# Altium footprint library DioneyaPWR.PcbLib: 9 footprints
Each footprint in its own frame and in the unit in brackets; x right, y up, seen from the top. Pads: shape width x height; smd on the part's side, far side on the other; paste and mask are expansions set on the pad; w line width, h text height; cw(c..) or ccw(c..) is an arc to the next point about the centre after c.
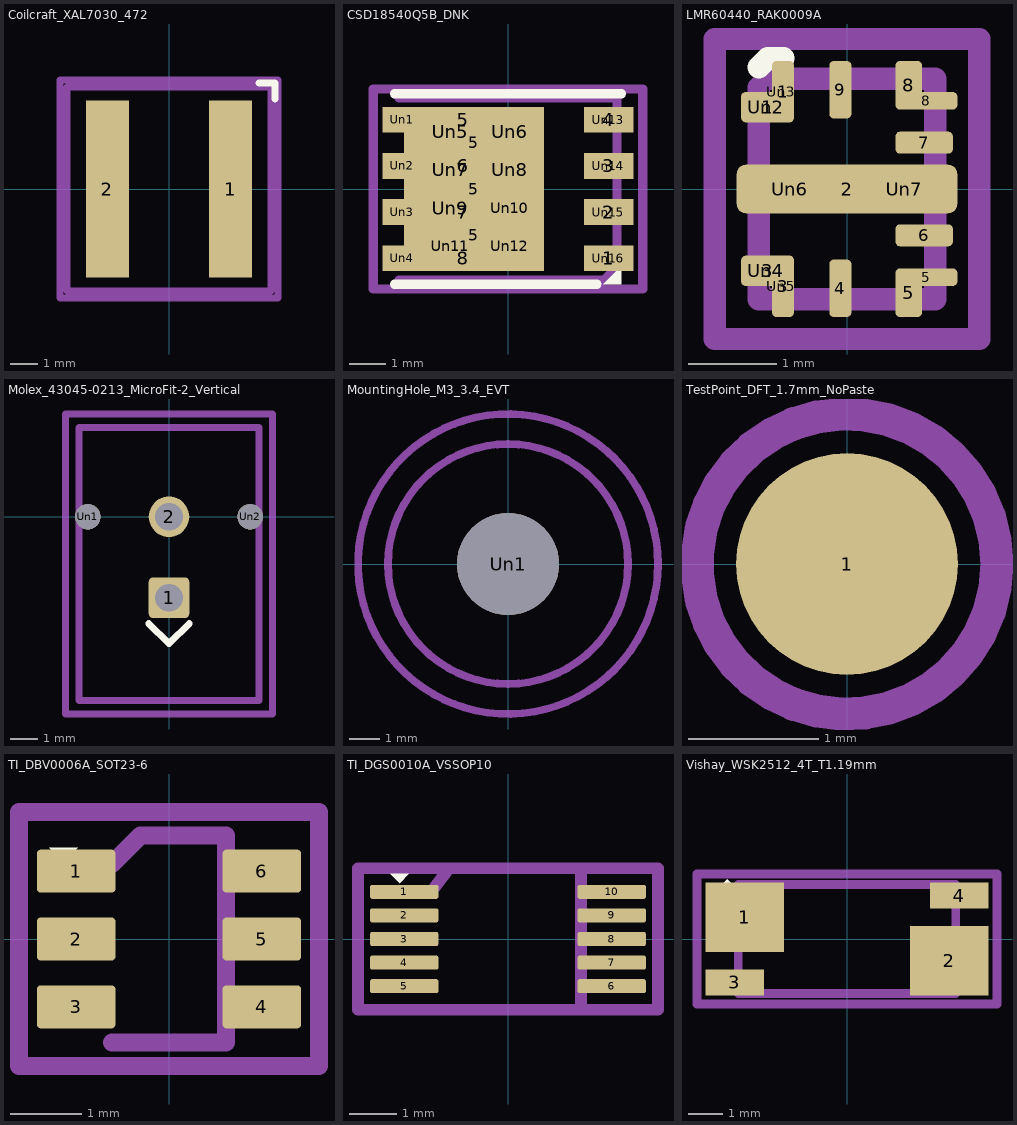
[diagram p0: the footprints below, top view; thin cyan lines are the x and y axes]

## Coilcraft_XAL7030_472 [mm]
pads (2):
  rect 1.58x6.5 smd: 1(2.26,0) 2(-2.26,0)
F.SilkS:
  lines w0.254: 3.3,3.9 3.9,3.9 3.9,3.3
F.Fab:
  lines w0.254: -3.75,-3.75 -3.75,3.75 3.75,3.75 3.75,-3.75 -3.75,-3.75
F.CrtYd:
  lines w0.254: -4,-4 -4,4 4,4 4,-4 -4,-4

## CSD18540Q5B_DNK [mm]
pads (27):
  rect 1.372x0.71 smd: 1(2.77,-1.905) 2(2.77,-0.635) 3(2.77,0.635) 4(2.77,1.905)
  rect 4.44x0.71 smd: 5(-1.236,1.905) 6(-1.236,0.635) 7(-1.236,-0.635) 8(-1.236,-1.905)
  rect 3.85x0.56 smd: 5(-0.941,-1.27) 5(-0.941,0) 5(-0.941,1.27)
  rect 0.766x0.508 on Top Paste: Un1(-2.91,1.905) Un2(-2.91,0.635) Un3(-2.91,-0.635) Un4(-2.91,-1.905)
  rect 1.294x0.746 on Top Paste: Un5(-1.594,1.569) Un6(0.05,1.569) Un7(-1.594,0.523) Un8(0.05,0.523) Un9(-1.594,-0.523) Un10(0.05,-0.523) Un11(-1.594,-1.569) Un12(0.05,-1.569)
  rect 1.072x0.562 on Top Paste: Un13(2.758,1.905) Un14(2.758,0.635) Un15(2.758,-0.635) Un16(2.758,-1.905)
F.SilkS:
  region: 3.12,-2.62 2.62,-2.62 3.12,-2.12
  lines w0.254: -3.12,-2.62 2.45,-2.62 ; -3.12,2.62 3.12,2.62
F.Fab:
  lines w0.254: -3,-2.5 2.65,-2.5 3,-2.15 3,2.5 -3,2.5
F.CrtYd:
  lines w0.254: -3.706,-2.75 -3.706,2.75 3.706,2.75 3.706,-2.75 -3.706,-2.75

## LMR60440_RAK0009A [mm]
pads (20):
  rrect29% 0.6x0.345 smd: 1(-0.9,0.927) 3(-0.9,-0.927)
  rrect40% 0.25x0.695 smd: 1(-0.725,1.102) 3(-0.725,-1.102)
  rrect36% 2.5x0.55 smd: 2(0,0)
  rrect40% 0.25x0.65 smd: 4(-0.075,-1.125) 9(-0.075,1.125)
  rrect33% 0.3x0.55 smd: 5(0.7,-1.175) 8(0.7,1.175)
  rrect50% 0.7x0.2 smd: 5(0.9,-1) 8(0.9,1)
  rrect40% 0.65x0.25 smd: 6(0.875,-0.525) 7(0.875,0.525)
  rect 0.01x0.01 on Top Solder: Un1(0,0)
  rrect29% 0.56x0.345 on Top Paste: Un2(-0.92,0.927) Un4(-0.92,-0.927)
  rrect48% 0.21x0.695 on Top Paste: Un3(-0.745,1.102) Un5(-0.745,-1.102)
  rrect24% 1.1x0.41 on Top Paste: Un6(-0.65,0)
  rrect33% 1.1x0.3 on Top Paste: Un7(0.65,0)
F.SilkS:
  lines w0.254: -1,1.38 -0.9,1.48 -0.72,1.48
F.Mask:
  region: -0.027,0.214 0.037,0.161 0.069,0.15 1.15,0.15 1.2,0.1 1.2,-0.1 1.15,-0.15 0.069,-0.15 0.037,-0.161 -0.027,-0.214 -0.059,-0.225 -1.15,-0.225 -1.2,-0.175 -1.2,0.175 -1.15,0.225 -0.059,0.225
F.Fab:
  lines w0.254: -1,1.15 -1,-1.25 1,-1.25 1,1.25 -0.9,1.25
F.CrtYd:
  lines w0.254: -1.5,-1.7 -1.5,1.7 1.5,1.7 1.5,-1.7 -1.5,-1.7

## Molex_43045-0213_MicroFit-2_Vertical [mm]
pads (4):
  rrect20% 1.5x1.5 hole 1.02: 1(0,-3)
  round 1.5 hole 1.02: 2(0,0)
  round 0.94 hole 0.94: Un1(-3,0) Un2(3,0)
F.SilkS:
  lines w0.254: -0.75,-3.95 0,-4.7 0.75,-3.95
F.Fab:
  lines w0.254: -3.325,-6.8 -3.325,3.3 3.325,3.3 3.325,-6.8 -3.325,-6.8
F.CrtYd:
  lines w0.254: -3.83,-7.3 -3.83,3.8 3.83,3.8 3.83,-7.3 -3.83,-7.3

## MountingHole_M3_3.4_EVT [mm]
pads (1):
  round 3.4 hole 3.4: Un1(0,0)
F.CrtYd:
  circle w0.254: c0,0 r5
Dwgs.User:
  circle w0.254: c0,0 r4

## TestPoint_DFT_1.7mm_NoPaste [mm]
pads (1):
  round 1.7 smd: 1(0,0)
F.CrtYd:
  circle w0.254: c0,0 r1.15

## TI_DBV0006A_SOT23-6 [mm]
pads (6):
  rrect17% 1.1x0.6 smd: 1(-1.3,0.95) 2(-1.3,0) 3(-1.3,-0.95) 4(1.3,-0.95) 5(1.3,0) 6(1.3,0.95)
F.SilkS:
  region: -1.48,1.08 -1.68,1.28 -1.28,1.28
F.Fab:
  lines w0.254: -0.8,-1.45 0.8,-1.45 0.8,1.45 -0.4,1.45 -0.8,1.05
F.CrtYd:
  lines w0.254: -2.1,-1.78 -2.1,1.78 2.1,1.78 2.1,-1.78 -2.1,-1.78

## TI_DGS0010A_VSSOP10 [mm]
pads (10):
  rrect33% 1.45x0.3 smd: 1(-2.2,1) 2(-2.2,0.5) 3(-2.2,0) 4(-2.2,-0.5) 5(-2.2,-1) 6(2.2,-1) 7(2.2,-0.5) 8(2.2,0) 9(2.2,0.5) 10(2.2,1)
F.SilkS:
  region: -2.3,1.18 -2.5,1.38 -2.1,1.38
F.Fab:
  lines w0.254: -1.55,-1.5 1.55,-1.5 1.55,1.5 -1.25,1.5 -1.55,1.1
F.CrtYd:
  lines w0.254: -3.18,-1.5 -3.18,1.5 3.18,1.5 3.18,-1.5 -3.18,-1.5

## Vishay_WSK2512_4T_T1.19mm [mm]
pads (4):
  rect 2.29x2.03 smd: 1(-2.985,0.635) 2(2.985,-0.635)
  rect 1.7x0.76 smd: 3(-3.28,-1.27) 4(3.28,1.27)
F.SilkS:
  region: -3.2,1.45 -3.8,1.45 -3.5,1.75
F.Fab:
  lines w0.254: -3.175,-1.59 -3.175,1.59 3.175,1.59 3.175,-1.59 -3.175,-1.59
F.CrtYd:
  lines w0.254: -4.38,-1.9 -4.38,1.9 4.38,1.9 4.38,-1.9 -4.38,-1.9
